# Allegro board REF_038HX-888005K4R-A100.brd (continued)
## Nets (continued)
D30105: D301.05
D30106: D301.06 SITE1.29(RXD1P)
D30107: D301.07
D30108: D301.08 SITE1.30(RXD1N)
D30109: D301.09
D30110: D301.10 SITE1.32(RXD2P)
D30111: D301.11
D30112: D301.12 SITE1.33(RXD2N)
D30113: D301.13
D30114: D301.14 SITE1.35(RXD3P)
D30115: D301.15
D30116: D301.16 SITE1.36(RXD3N)
D30201: D302.01
D30202: D302.02
D30203: D302.03
D30204: D302.04
D30205: D302.05
D30206: D302.06
D30207: D302.07
D30208: D302.08
D30209: D302.09
D30210: D302.10
D30211: D302.11
D30212: D302.12
D30213: D302.13
D30214: D302.14
D30215: D302.15
D30216: D302.16
D30501: D305.01
D30502: D305.02 SITE2.26(RXD0P)
D30503: D305.03
D30504: D305.04 SITE2.27(RXD0N)
D30505: D305.05
D30506: D305.06 SITE2.29(RXD1P)
D30507: D305.07
D30508: D305.08 SITE2.30(RXD1N)
D30509: D305.09
D30510: D305.10 SITE2.32(RXD2P)
D30511: D305.11
D30512: D305.12 SITE2.33(RXD2N)
D30513: D305.13
D30514: D305.14 SITE2.35(RXD3P)
D30515: D305.15
D30516: D305.16 SITE2.36(RXD3N)
D30601: D306.01
D30602: D306.02
D30603: D306.03
D30604: D306.04
D30605: D306.05
D30606: D306.06
D30607: D306.07
D30608: D306.08
D30609: D306.09
D30610: D306.10
D30611: D306.11
D30612: D306.12
D30613: D306.13
D30614: D306.14
D30615: D306.15
D30616: D306.16
DPS1_C1: DPS1.C01
DPS1_C5: DPS1.C05
DPS1_C11: DPS1.C11
DPS1_C15: DPS1.C15
DPS2_C1: DPS2.C01
DPS2_C5: DPS2.C05
DPS2_C11: DPS2.C11
DPS2_C15: DPS2.C15
DPS3_C1: DPS3.C01
DPS3_C5: DPS3.C05
DPS3_C11: DPS3.C11
DPS3_C15: DPS3.C15
DPS8_C1: DPS8.C01
DPS8_C5: DPS8.C05
DPS8_C11: DPS8.C11
DPS8_C15: DPS8.C15
MSDPS1_1F: DPS1.C03
MSDPS1_1GRD: DPS1.B02
MSDPS1_1GS: DPS1.A02
MSDPS1_1S: DPS1.C02
MSDPS1_2F: DPS1.C07
MSDPS1_2GRD: DPS1.B06
MSDPS1_2GS: DPS1.A06
MSDPS1_2S: DPS1.C06
MSDPS1_3F: DPS1.C13
MSDPS1_3GRD: DPS1.B12
MSDPS1_3GS: DPS1.A12
MSDPS1_3S: DPS1.C12
MSDPS1_4F: DPS1.C17
MSDPS1_4GRD: DPS1.B16
MSDPS1_4GS: DPS1.A16
MSDPS1_4S: DPS1.C16
MSDPS1_5F: DPS1.A03
MSDPS1_5GS: DPS1.B01
MSDPS1_5S: DPS1.B03
MSDPS1_6F: DPS1.A07
MSDPS1_6GS: DPS1.B05
MSDPS1_6S: DPS1.B07
MSDPS1_7F: DPS1.A13
MSDPS1_7GS: DPS1.B11
MSDPS1_7S: DPS1.B13
MSDPS1_8F: DPS1.A17
MSDPS1_8GS: DPS1.B15
MSDPS1_8S: DPS1.B17
MSDPS1_TR+: DPS1.A09
MSDPS1_TRVB-: DPS1.B09 SB1.2
MSDPS1_VB+: DPS1.C09
MSDPS2_1F: DPS2.C03
MSDPS2_1GRD: DPS2.B02
MSDPS2_1GS: DPS2.A02
MSDPS2_1S: DPS2.C02
MSDPS2_2F: DPS2.C07
MSDPS2_2GRD: DPS2.B06
MSDPS2_2GS: DPS2.A06
MSDPS2_2S: DPS2.C06
MSDPS2_3F: DPS2.C13
MSDPS2_3GRD: DPS2.B12
MSDPS2_3GS: DPS2.A12
MSDPS2_3S: DPS2.C12
MSDPS2_4F: DPS2.C17
MSDPS2_4GRD: DPS2.B16
MSDPS2_4GS: DPS2.A16
MSDPS2_4S: DPS2.C16
MSDPS2_5F: DPS2.A03
MSDPS2_5GS: DPS2.B01
MSDPS2_5S: DPS2.B03
MSDPS2_6F: DPS2.A07
MSDPS2_6GS: DPS2.B05
MSDPS2_6S: DPS2.B07
MSDPS2_7F: DPS2.A13
MSDPS2_7GS: DPS2.B11
MSDPS2_7S: DPS2.B13
MSDPS2_8F: DPS2.A17
MSDPS2_8GS: DPS2.B15
MSDPS2_8S: DPS2.B17
MSDPS2_TR+: DPS2.A09
MSDPS2_TRVB-: DPS2.B09 SB2.2
MSDPS2_VB+: DPS2.C09
MSDPS3_1F: DPS3.C03
MSDPS3_1GRD: DPS3.B02
MSDPS3_1GS: DPS3.A02
MSDPS3_1S: DPS3.C02
MSDPS3_2F: DPS3.C07
MSDPS3_2GRD: DPS3.B06
MSDPS3_2GS: DPS3.A06
MSDPS3_2S: DPS3.C06
MSDPS3_3F: DPS3.C13
MSDPS3_3GRD: DPS3.B12
MSDPS3_3GS: DPS3.A12
MSDPS3_3S: DPS3.C12
MSDPS3_4F: DPS3.C17
MSDPS3_4GRD: DPS3.B16
MSDPS3_4GS: DPS3.A16
MSDPS3_4S: DPS3.C16
MSDPS3_5F: DPS3.A03
MSDPS3_5GS: DPS3.B01
MSDPS3_5S: DPS3.B03
MSDPS3_6F: DPS3.A07
MSDPS3_6GS: DPS3.B05
MSDPS3_6S: DPS3.B07
MSDPS3_7F: DPS3.A13
MSDPS3_7GS: DPS3.B11
MSDPS3_7S: DPS3.B13
MSDPS3_8F: DPS3.A17
MSDPS3_8GS: DPS3.B15
MSDPS3_8S: DPS3.B17
MSDPS3_TR+: DPS3.A09
MSDPS3_TRVB-: DPS3.B09 SB3.2
MSDPS3_VB+: DPS3.C09
MSDPS8_1F: DPS8.C03
MSDPS8_1GRD: DPS8.B02
MSDPS8_1GS: DPS8.A02
MSDPS8_1S: DPS8.C02
MSDPS8_2F: DPS8.C07
MSDPS8_2GRD: DPS8.B06
MSDPS8_2GS: DPS8.A06
MSDPS8_2S: DPS8.C06
MSDPS8_3F: DPS8.C13
MSDPS8_3GRD: DPS8.B12
MSDPS8_3GS: DPS8.A12
MSDPS8_3S: DPS8.C12
MSDPS8_4F: DPS8.C17
MSDPS8_4GRD: DPS8.B16
MSDPS8_4GS: DPS8.A16
MSDPS8_4S: DPS8.C16
MSDPS8_5F: DPS8.A03
MSDPS8_5GS: DPS8.B01
MSDPS8_5S: DPS8.B03
MSDPS8_6F: DPS8.A07
MSDPS8_6GS: DPS8.B05
MSDPS8_6S: DPS8.B07
MSDPS8_7F: DPS8.A13
MSDPS8_7GS: DPS8.B11
MSDPS8_7S: DPS8.B13
MSDPS8_8F: DPS8.A17
MSDPS8_8GS: DPS8.B15
MSDPS8_8S: DPS8.B17
MSDPS8_TR+: DPS8.A09
MSDPS8_TRVB-: DPS8.B09 SB8.2
MSDPS8_VB+: DPS8.C09
S1_1AUX+: K9.4 R129.1
S1_1AUX-: K9.5 R130.1
S1_1SPI_CSN: K15.5 K19.6
S1_1SPI_SCK: K15.4 K19.3
S1_1SPI_SDI: K14.5 K20.6
S1_1SPI_SDO: K14.4 K20.3
S1_2AUX+: C3.1 R1.2 R3.1 R129.2
S1_2AUX-: C4.1 R2.2 R4.2 R130.2
S1_AUXCH+: K9.3 K12.3 SITE1.21(AUXCHP)
S1_AUXCH-: K9.6 K12.6 SITE1.20(AUXCHN)
S1_ISP_1LOCK: K33.3 R118.2
S1_SPI_1_CSN: K19.7 R87.1 U1.1(CS#)
S1_SPI_1_SCK: K19.2 R91.1 U1.6(SCLK)
S1_SPI_1_SDI: K20.7 R127.1
S1_SPI_1_SDO: K20.2 R125.1
S1_SPI_2_CSN: K19.5 R94.1 U2.1(CS#)
S1_SPI_2_SCK: K19.4 R98.1 U2.6(SCLK)
S1_SPI_2_SDI: K20.5 R128.1
S1_SPI_2_SDO: K20.4 R126.1
S1_SPI_11_SDI: R88.1 R127.2 U1.2(SO)
S1_SPI_11_SDO: R92.1 R125.2 U1.5(SI)
S1_SPI_22_SDI: R95.1 R128.2 U2.2(SO)
S1_SPI_22_SDO: R99.1 R126.2 U2.5(SI)
S1_SPI_CSN: K15.6 SITE1.43(SPI_CSN)
S1_SPI_SCK: K15.3 SITE1.42(SPI_SCK)
S1_SPI_SDI: K14.6 SITE1.44(SPI_SDI)
S1_SPI_SDO: K14.3 SITE1.41(SPI_SDO)
S1_XTAL_IN: K18.3 SITE1.109(XTAL_IN) TP_XTAL_IN.1(TP)
S1_XTAL_OUT: K18.6 SITE1.110(XTAL_OUT) TP_XTAL_OUT.1(TP)
S2_1AUX+: UNK2K9.4 UNK2R129.1
S2_1AUX-: UNK2K9.5 UNK2R130.1
S2_1SPI_CSN: UNK2K15.5 UNK2K19.6
S2_1SPI_SCK: UNK2K15.4 UNK2K19.3
S2_1SPI_SDI: UNK2K14.5 UNK2K20.6
S2_1SPI_SDO: UNK2K14.4 UNK2K20.3
S2_2AUX+: UNK2C3.1 UNK2R1.2 UNK2R3.1 UNK2R129.2
S2_2AUX-: UNK2C4.1 UNK2R2.2 UNK2R4.2 UNK2R130.2
S2_AUXCH+: SITE2.21(AUXCHP) UNK2K9.3 UNK2K12.3
S2_AUXCH-: SITE2.20(AUXCHN) UNK2K9.6 UNK2K12.6
S2_ISP_1LOCK: UNK2K33.3 UNK2R118.2
S2_SPI_1_CSN: UNK2K19.7 UNK2R87.1 UNK2U1.1
S2_SPI_1_SCK: UNK2K19.2 UNK2R91.1 UNK2U1.6
S2_SPI_1_SDI: UNK2K20.7 UNK2R127.1
S2_SPI_1_SDO: UNK2K20.2 UNK2R125.1
S2_SPI_2_CSN: UNK2K19.5 UNK2R94.1 UNK2U2.1
S2_SPI_2_SCK: UNK2K19.4 UNK2R98.1 UNK2U2.6
S2_SPI_2_SDI: UNK2K20.5 UNK2R128.1
S2_SPI_2_SDO: UNK2K20.4 UNK2R126.1
S2_SPI_11_SDI: UNK2R88.1 UNK2R127.2 UNK2U1.2
S2_SPI_11_SDO: UNK2R92.1 UNK2R125.2 UNK2U1.5
S2_SPI_22_SDI: UNK2R95.1 UNK2R128.2 UNK2U2.2
S2_SPI_22_SDO: UNK2R99.1 UNK2R126.2 UNK2U2.5
S2_SPI_CSN: SITE2.43(SPI_CSN) UNK2K15.6
S2_SPI_SCK: SITE2.42(SPI_SCK) UNK2K15.3
S2_SPI_SDI: SITE2.44(SPI_SDI) UNK2K14.6
S2_SPI_SDO: SITE2.41(SPI_SDO) UNK2K14.3
S2_XTAL_IN: SITE2.109(XTAL_IN) UNK2K18.3 UNK2TP_XTAL_IN.1
S2_XTAL_OUT: SITE2.110(XTAL_OUT) UNK2K18.6 UNK2TP_XTAL_OUT.1
SK1_2: SK1.2 SK1_2.1(TP)
SK1_3: SK1.3 SK1_3.1(TP)
SK1_4: SK1.4 SK1_4.1(TP)
SK1_5: SK1.5 SK1_5.1(TP)
SK1_6: SK1.6 SK1_6.1(TP)
SK1_7: SK1.7 SK1_7.1(TP)
SK2_2: SK2.2 SK2_2.1(TP)
SK2_3: SK2.3 SK2_3.1(TP)
SK2_4: SK2.4 SK2_4.1(TP)
SK2_5: SK2.5 SK2_5.1(TP)
SK2_6: SK2.6 SK2_6.1(TP)
SK2_7: SK2.7 SK2_7.1(TP)
UDBGND: BD29.2 BD30.2 BD31.2 BD32.2 BD33.2 BD34.2 BD35.2 BD36.2 BD37.2 BD38.2 BD39.2 BD40.2 CB1.2 CB2.2 CB3.2 CB4.2 CB5.2 CB6.2 CB7.2 CB8.2 CB19.1 LD902.2(B) UB1.1(A0) UB1.2(A1) UB1.3(A2) UB1.4(GND) UB1.7(WP) UTL1.A02 UTL1.A08 UTL1.A10 UTL1.A12 UTL1.A14 UTL1.B01 UTL1.B07 UTL1.B09 UTL1.B11 UTL1.B13 UTL2.A02 UTL2.A08 UTL2.A10 UTL2.A12 UTL2.A14 UTL2.B01 UTL2.B07 UTL2.B09 UTL2.B11 UTL2.B13 UTL3.A02 UTL3.A08 UTL3.A10 UTL3.A12 UTL3.A14 UTL3.B01 UTL3.B07 UTL3.B09 UTL3.B11 UTL3.B13 UTL4.A02 UTL4.A08 UTL4.A10 UTL4.A12 UTL4.A14 UTL4.B01 UTL4.B07 UTL4.B09 UTL4.B11 UTL4.B13
UT1_PDCF: UTL1.B15
UT1_PDCS: UTL1.A15
UT1_PGDS: UTL1.A16
UT1_PGRD: UTL1.B16
UT1_UP5V: BR902.1 CB1.1 CB2.1 CB3.1 CB4.1 CB5.1 CB6.1 CB7.1 CB8.1 CB19.2 CT1.2 K1.1(V+) K2.1(V+) K3.1(V+) K4.1(V+) K5.1(V+) K6.1(V+) K7.1(V+) K8.1(V+) K9.1(V+) K10.1(V+) K11.1(V+) K12.1(V+) K13.1(V+) K14.1(V+) K15.1(V+) K16.1(V+) K17.1(V+) K18.1(V+) K19.1(V+) K20.1(V+) K21.1(V+) K22.1(V+) K23.1(V+) K24.1(V+) K25.1(V+) K26.1(V+) K27.1(V+) K28.1(V+) K29.1(V+) K30.1(V+) K31.1(V+) K33.1(V+) K34.1(V+) K36.1(V+) K37.1(V+) K39.1(V+) K40.1(V+) K42.1(V+) RB1.1 RB2.1 RT1.1 RT2.1 RT5.2 RT6.2 RT7.1 RT8.1 SK1.1(V+) SK2.1(V+) UB1.8(VCC) UNK2CT1.2 UNK2K1.1 UNK2K2.1 UNK2K3.1 UNK2K4.1 UNK2K5.1 UNK2K6.1 UNK2K7.1 UNK2K8.1 UNK2K9.1 UNK2K10.1 UNK2K11.1 UNK2K12.1 UNK2K13.1 UNK2K14.1 UNK2K15.1 UNK2K16.1 UNK2K17.1 UNK2K18.1 UNK2K19.1 UNK2K20.1 UNK2K21.1 UNK2K22.1 UNK2K23.1 UNK2K24.1 UNK2K25.1 UNK2K26.1 UNK2K27.1 UNK2K28.1 UNK2K29.1 UNK2K30.1 UNK2K31.1 UNK2K33.1 UNK2K34.1 UNK2K36.1 UNK2K37.1 UNK2K39.1 UNK2K40.1 UNK2K42.1 UNK2RT1.1 UNK2RT2.1 UNK2RT5.2 UNK2RT6.2 UNK2RT7.1 UNK2RT8.1 UNK2SK1.1 UNK2SK2.1 UNK2UT1.8 UT1.8(VDD) UT_UP5V.1(TP) UTL1.A05 UTL1.B04 UTL2.A05 UTL2.B04 UTL3.A05 UTL3.B04 UTL4.A05 UTL4.B04
UT1_URW00: K13.8(V-) UTL1.A01
UT1_URW01: K28.8(V-) UTL1.B02
UT1_URW02: K14.8(V-) UTL1.A03
UT1_URW03: K33.8(V-) UTL1.B03
UT1_URW04: K20.8(V-) UTL1.A04
UT1_URW05: K10.8(V-) UTL1.B05
UT1_URW06: K15.8(V-) UTL1.A06
UT1_UW07: SK2.8(V-) UTL1.B06
UT1_UW08: K19.8(V-) UTL1.A07
UT1_UW09: K25.8(V-) K27.8(V-) UTL1.B08
UT1_UW10: K9.8(V-) UTL1.A09
UT1_UW11: K26.8(V-) UTL1.B10
UT1_UW12: K12.8(V-) UTL1.A11
UT1_UW13: SK1.8(V-) UTL1.B12
UT1_UW14: K23.8(V-) UTL1.A13
UT1_UW15: K22.8(V-) K24.8(V-) UTL1.B14
UT2_PDCF: UTL2.B15
UT2_PDCS: UTL2.A15
UT2_PGDS: UTL2.A16
UT2_PGRD: UTL2.B16
UT2_URW00: UNK2SK2.8 UTL2.A01
UT2_URW01: UNK2K25.8 UNK2K27.8 UTL2.B02
UT2_URW02: UNK2K10.8 UTL2.A03
UT2_URW03: UNK2K26.8 UTL2.B03
UT2_URW04: UNK2SK1.8 UTL2.A04
UT2_URW05: UNK2K22.8 UNK2K24.8 UTL2.B05
UT2_URW06: UNK2K33.8 UTL2.A06
UT2_UW07: UNK2K23.8 UTL2.B06
UT2_UW08: UNK2K28.8 UTL2.A07
UT2_UW09: UNK2K9.8 UTL2.B08
UT2_UW10: UNK2K13.8 UTL2.A09
UT2_UW11: UNK2K12.8 UTL2.B10
UT2_UW12: UNK2K14.8 UTL2.A11
UT2_UW13: UNK2K19.8 UTL2.B12
UT2_UW14: UNK2K20.8 UTL2.A13
UT2_UW15: UNK2K15.8 UTL2.B14
UT3_PDCF: UTL3.B15
UT3_PDCS: UTL3.A15
UT3_PGDS: UTL3.A16
UT3_PGRD: UTL3.B16
UT3_URW00: K30.8(V-) UTL3.A01
UT3_URW01: UNK2K3.8 UNK2K4.8 UTL3.B02
UT3_URW02: K21.8(V-) K29.8(V-) UTL3.A03
UT3_URW03: UNK2K1.8 UNK2K2.8 UTL3.B03
UT3_URW04: K16.8(V-) K17.8(V-) UTL3.A04
UT3_URW05: UNK2K5.8 UNK2K6.8 UTL3.B05
UT3_URW06: K7.8(V-) UTL3.A06
UT3_UW07: UNK2K7.8 UTL3.B06
UT3_UW08: K8.8(V-) K11.8(V-) UTL3.A07
UT3_UW09: UNK2K8.8 UNK2K11.8 UTL3.B08
UT3_UW10: K5.8(V-) K6.8(V-) UTL3.A09
UT3_UW11: UNK2K16.8 UNK2K17.8 UTL3.B10
UT3_UW12: K3.8(V-) K4.8(V-) UTL3.A11
UT3_UW13: UNK2K30.8 UTL3.B12
UT3_UW14: K1.8(V-) K2.8(V-) UTL3.A13
UT3_UW15: UNK2K21.8 UNK2K29.8 UTL3.B14
UT4_PDCF: UTL4.B15
UT4_PDCS: UTL4.A15
UT4_PGDS: UTL4.A16
UT4_PGRD: UTL4.B16
UT4_URW00: UNK2K37.12 UTL4.A01
UT4_URW01: UNK2K39.12 UTL4.B02
UT4_URW02: UNK2K42.12 UTL4.A03
UT4_URW03: UNK2K36.12 UTL4.B03
UT4_URW04: UNK2K34.12 UTL4.A04
UT4_URW05: UNK2K31.12 UTL4.B05
UT4_URW06: UNK2K40.12 UTL4.A06
UT4_UW07: UNK2K18.8 UTL4.B06
UT4_UW08: K37.12(V-) UTL4.A07
UT4_UW09: K18.8(V-) UTL4.B08
UT4_UW10: K39.12(V-) UTL4.A09
UT4_UW11: K34.12(V-) UTL4.B10
UT4_UW12: K42.12(V-) UTL4.A11
UT4_UW13: K40.12(V-) UTL4.B12
UT4_UW14: K36.12(V-) UTL4.A13
UT4_UW15: K31.12(V-) UTL4.B14
N23628089: BR902.2 LD902.1(A)
N24574244: J2.1 R89.1
N24574268: J3.1 R96.1
N24574272: J3.3 R93.1
N24574311: R90.1 U1.7(HOLD#)
N24574358: J2.2 U1.3(WP#)
N24574376: R97.1 U2.7(HOLD#)
N24574426: J3.2 U2.3(WP#)
N24574578: J2.3 R86.1
N24632959: J1.2 K10.4 R85.2 S1_RST_N.2 SW1.3 SW1.4
N24632988: C7.1 J1.1
N24641483: K25.3 R55.2
N24641485: K25.4 R56.1
N24641487: K25.6 R57.2
N24641489: K25.5 R58.1
N24641552: K26.3 R59.2
N24641554: K26.4 R60.1
N24641556: K26.6 R61.2
N24641558: K26.5 R62.1
N24641612: K27.5 R66.1
N24641614: K27.6 R65.2
N24642432: K22.6 R45.2
N24642434: K22.5 R46.1
N24642442: K23.3 R47.2
N24642444: K23.4 R48.1
N24642446: K23.6 R49.2
N24642448: K23.5 R50.1
N24642468: K24.3 R51.2
N24642486: K24.4 R52.1
N24642488: K24.6 R53.2
N24642490: K24.5 R54.1
N24780353: K12.4 R131.1
N24780370: K12.5 R132.1
N24787993: CA21.1 K34.5
N24789529: CA23.1 K36.5 K36.8
N24789779: CA24.1 K37.5
N24793751: RT3.1 RT5.1 UT1.3(A0)
N24793759: RT4.1 RT6.1 UT1.4(A1)
N24793795: RT7.2 UT1.6(CT)
N24793797: RT8.2 UT1.5(INT)
N25306310: K22.3 R102.2
N25306320: K22.4 R103.1
N25306354: K27.3 R104.2
N25306364: K27.4 R105.1
N25330426: CA29.1 K42.5
N25334489: CA26.1 K39.5
N25337760: CA34.1 K31.5
N25339188: CA27.1 K40.5
N25362248: K33.2 R82.1
N25362250: K33.4 R117.1
N25362465: K11.3 R39.2
N25362471: K11.4 R40.1
N25362509: K8.5 R38.1
N25362552: K8.3 R35.2
N25362554: K8.4 R36.1
N25362556: K8.6 R37.2
N25362573: K11.6 R41.2
N25362575: K11.5 R42.1
N25362658: K3.5 R18.1
N25362663: K3.6 R17.2
N25362668: K3.4 R16.1
N25362670: K3.3 R15.2
N25362705: K1.5 R10.1
N25362707: K1.6 R9.2
N25362709: K1.4 R8.1
N25362711: K1.3 R7.2
N25362734: K2.3 R11.2
N25362739: K2.4 R12.1
N25362741: K4.5 R22.1
N25362761: K4.3 R19.2
N25362763: K4.4 R20.1
N25362765: K4.6 R21.2
N25362815: K5.5 R26.1
N25362863: K5.3 R23.2
N25362865: K5.4 R24.1
N25362867: K5.6 R25.2
N25363066: K16.3 R67.2
N25363068: K16.4 R68.1
N25363070: K16.5 R70.1
N25363072: K16.6 R69.2
N25363098: K17.3 R71.2
N25363100: K17.4 R72.1
N25363118: K17.5 R74.1
N25363120: K17.6 R73.2
N25363130: K21.3 R75.2
N25363148: K21.4 R76.1
N25363150: K21.5 R78.1
N25363152: K21.6 R77.2
N25363178: K29.3 R79.2
N25363180: K29.4 R80.1
N25363198: K2.5 R14.1
N25363200: K2.6 R13.2
N25363358: K29.6 R43.2
N25363360: K29.5 R44.1
N25363376: K30.3 R63.2
N25363378: K30.4 R64.1
N25363404: K30.5 R101.1
N25363406: K30.6 R100.2
N25363469: K6.5 R30.1
N25363533: K6.3 R27.2
N25363535: K6.4 R28.1
N25363537: K6.6 R29.2
N25363539: K7.5 R34.1
N25363555: K7.3 R31.2
N25363557: K7.4 R32.1
N25363559: K7.6 R33.2
N25363681: K18.4 R5.1 R6.2
N25363685: K18.5 R6.1 R133.1
N25363701: C5.1 R133.2 Y1.1 Y2.1
N25363703: C6.1 R5.2 Y1.3 Y2.3
N25363863: K13.5 R120.2
N25363865: K13.4 R119.2
N25363959: J5.1 K28.5 R84.2
N25363975: J4.1 K28.4 R83.2
N25462044: CA37.1 K39.8
N25462912: CA40.1 K42.8
N25463486: CA28.1 K40.8
N25464528: CA25.1 K37.8
N25465136: CA22.1 K34.8
N25611014: UNK2J1.2 UNK2K10.4 UNK2R85.2 UNK2S1_RST_N.2
N25611025: UNK2C7.1 UNK2J1.1
N25611039: UNK2K25.3 UNK2R55.2
N25611040: UNK2K25.4 UNK2R56.1
N25611041: UNK2K25.6 UNK2R57.2
N25611042: UNK2K25.5 UNK2R58.1
N25611050: UNK2K26.3 UNK2R59.2
N25611051: UNK2K26.4 UNK2R60.1
N25611052: UNK2K26.6 UNK2R61.2
N25611053: UNK2K26.5 UNK2R62.1
N25611061: UNK2K27.5 UNK2R66.1
N25611062: UNK2K27.6 UNK2R65.2
N25611083: UNK2K22.6 UNK2R45.2
N25611084: UNK2K22.5 UNK2R46.1
N25611085: UNK2K23.3 UNK2R47.2
N25611086: UNK2K23.4 UNK2R48.1
N25611087: UNK2K23.6 UNK2R49.2
N25611088: UNK2K23.5 UNK2R50.1
N25611096: UNK2K24.3 UNK2R51.2
N25611097: UNK2K24.4 UNK2R52.1
N25611098: UNK2K24.6 UNK2R53.2
N25611099: UNK2K24.5 UNK2R54.1
N25611164: UNK2K12.4 UNK2R131.1
N25611166: UNK2K12.5 UNK2R132.1
N25611179: UNK2K22.3 UNK2R102.2
N25611180: UNK2K22.4 UNK2R103.1
N25611181: UNK2K27.3 UNK2R104.2
N25611182: UNK2K27.4 UNK2R105.1
N25611602: UNK2K33.2 UNK2R82.1
N25611603: UNK2K33.4 UNK2R117.1
N25611639: UNK2K11.3 UNK2R39.2
N25611640: UNK2K11.4 UNK2R40.1
N25611647: UNK2K8.5 UNK2R38.1
N25611655: UNK2K8.3 UNK2R35.2
N25611656: UNK2K8.4 UNK2R36.1
N25611657: UNK2K8.6 UNK2R37.2
N25611658: UNK2K11.6 UNK2R41.2
N25611659: UNK2K11.5 UNK2R42.1
N25611669: UNK2K3.5 UNK2R18.1
N25611670: UNK2K3.6 UNK2R17.2
N25611671: UNK2K3.4 UNK2R16.1
N25611672: UNK2K3.3 UNK2R15.2
N25611686: UNK2K1.5 UNK2R10.1
N25611687: UNK2K1.6 UNK2R9.2
N25611688: UNK2K1.4 UNK2R8.1
N25611689: UNK2K1.3 UNK2R7.2
N25611697: UNK2K2.3 UNK2R11.2
N25611700: UNK2K2.4 UNK2R12.1
N25611701: UNK2K4.5 UNK2R22.1
N25611709: UNK2K4.3 UNK2R19.2
N25611710: UNK2K4.4 UNK2R20.1
N25611711: UNK2K4.6 UNK2R21.2
N25611712: UNK2K5.5 UNK2R26.1
N25611720: UNK2K5.3 UNK2R23.2
N25611721: UNK2K5.4 UNK2R24.1
N25611722: UNK2K5.6 UNK2R25.2
N25611735: UNK2K16.3 UNK2R67.2
N25611736: UNK2K16.4 UNK2R68.1
N25611737: UNK2K16.5 UNK2R70.1
N25611738: UNK2K16.6 UNK2R69.2
N25611739: UNK2K17.3 UNK2R71.2
N25611740: UNK2K17.4 UNK2R72.1
N25611741: UNK2K17.5 UNK2R74.1
N25611742: UNK2K17.6 UNK2R73.2
N25611743: UNK2K21.3 UNK2R75.2
N25611744: UNK2K21.4 UNK2R76.1
N25611745: UNK2K21.5 UNK2R78.1
N25611746: UNK2K21.6 UNK2R77.2
N25611747: UNK2K29.3 UNK2R79.2
N25611748: UNK2K29.4 UNK2R80.1
N25611749: UNK2K2.5 UNK2R14.1
N25611750: UNK2K2.6 UNK2R13.2
N25611839: UNK2K29.6 UNK2R43.2
N25611840: UNK2K29.5 UNK2R44.1
N25611845: UNK2K30.3 UNK2R63.2
N25611846: UNK2K30.4 UNK2R64.1
N25611847: UNK2K30.5 UNK2R101.1
N25611848: UNK2K30.6 UNK2R100.2
N25611859: UNK2K6.5 UNK2R30.1
N25611867: UNK2K6.3 UNK2R27.2
N25611868: UNK2K6.4 UNK2R28.1
N25611869: UNK2K6.6 UNK2R29.2
N25611870: UNK2K7.5 UNK2R34.1
N25611878: UNK2K7.3 UNK2R31.2
N25611879: UNK2K7.4 UNK2R32.1
N25611880: UNK2K7.6 UNK2R33.2
N25611892: UNK2K18.4 UNK2R5.1 UNK2R6.2
N25611894: UNK2K18.5 UNK2R6.1 UNK2R133.1
N25611895: UNK2C5.1 UNK2R133.2 UNK2Y1.1 UNK2Y2.1
N25611896: UNK2C6.1 UNK2R5.2 UNK2Y1.3 UNK2Y2.3
N25611925: UNK2K13.5 UNK2R120.2
N25611926: UNK2K13.4 UNK2R119.2
N25611946: UNK2J5.1 UNK2K28.5 UNK2R84.2
N25611950: UNK2J4.1 UNK2K28.4 UNK2R83.2
N25615773: UNK2J2.1 UNK2R89.1
N25615777: UNK2J3.1 UNK2R96.1
N25615779: UNK2J3.3 UNK2R93.1
N25615786: UNK2R90.1 UNK2U1.7
N25615811: UNK2J2.2 UNK2U1.3
N25615820: UNK2R97.1 UNK2U2.7
N25615847: UNK2J3.2 UNK2U2.3
N25615858: UNK2J2.3 UNK2R86.1
N25616611: UNK2CA21.1 UNK2K34.5
N25616617: UNK2CA23.1 UNK2K36.5 UNK2K36.8
N25616622: UNK2CA24.1 UNK2K37.5
N25616748: UNK2CA29.1 UNK2K42.5
N25616755: UNK2CA26.1 UNK2K39.5
N25616834: UNK2CA34.1 UNK2K31.5
N25616842: UNK2CA27.1 UNK2K40.5
N25616987: UNK2CA37.1 UNK2K39.8
N25616993: UNK2CA40.1 UNK2K42.8
N25616997: UNK2CA28.1 UNK2K40.8
N25616999: UNK2CA25.1 UNK2K37.8
N25617005: UNK2CA22.1 UNK2K34.8
N25619537: UNK2RT3.1 UNK2RT5.1 UNK2UT1.3
N25619539: UNK2RT4.1 UNK2RT6.1 UNK2UT1.4
N25619557: UNK2RT7.2 UNK2UT1.6
N25619558: UNK2RT8.2 UNK2UT1.5

Pads without a net: CSDPS225 A17 B17 C17 D17; CSDPS229 A17 B17 C17 D17; CSDPS425 A17 B17 C17 D17; CSDPS429 A17 B17 C17 D17; D101/D501 A1 A2 A3 A4 A5 A6 A7 A8 A9 A10 A11 A12 A13 A14 A15 A16 A17 B1 B2 B3 B4 B5 B6 B7 B8 B9 B10 B11 B12 B13 B14 B15 B16 B17 C1 C2 C3 C4 C5 C6 C7 C8 C9 C10 C11 C12 C13 C14 C15 C16 C17 D2 D3 D4 D5 D6 D7 D8 D9 D10 D11 D12 D13 D14 D15 D16; D102 17 A17 B17; D103 17 A17 B17; D104 17 A17 B17; D105/D505 A1 A2 A3 A4 A5 A6 A7 A8 A9 A10 A11 A12 A13 A14 A15 A16 A17 B1 B2 B3 B4 B5 B6 B7 B8 B9 B10 B11 B12 B13 B14 B15 B16 B17 C1 C2 C3 C4 C5 C6 C7 C8 C9 C10 C11 C12 C13 C14 C15 C16 C17 D2 D3 D4 D5 D6 D7 D8 D9 D10 D11 D12 D13 D14 D15 D16; D106 17 A17 B17; D107 17 A17 B17; D108 17 A17 B17; D109 17 A17 B17; D110 17 A17 B17; D111 17 A17 B17; D112 17 A17 B17; D113 17 A17 B17; D114 17 A17 B17; D115 17 A17 B17; D116 17 A17 B17; D117 17 A17 B17; D118 17 A17 B17; D119 17 A17 B17; D120 17 A17 B17; D121 17 A17 B17; D122 17 A17 B17; D123 17 A17 B17; D124 17 A17 B17; D226 01 02 03 04 05 06 07 08 09 10 11 12 13 14 15 16 17; D227 01 02 03 04 05 06 07 08 09 10 11 12 13 14 15 16 17; D228 01 02 03 04 05 06 07 08 09 10 11 12 13 14 15 16 17; D230 01 02 03 05 06 07 08 09 10 11 12 13 14 15 16 17; D301 17 A17 B17; D302 17 A17 B17; D305 17 A17 B17; D306 17 A17 B17; D426 01 02 03 04 05 06 07 08 09 10 11 12 13 14 15 16 17; D427 01 02 03 04 05 06 07 08 09 10 11 12 13 14 15 16 17; D428 01 02 03 04 05 06 07 08 09 10 11 12 13 14 15 16 17; D430 01 02 03 04 05 06 07 08 09 10 11 12 13 14 15 16 17; DPS1 A04 A08 A10 A14 B04 B08 B10 B14 C04 C08 C10 C14; DPS2 A04 A08 A10 A14 B04 B08 B10 B14 C04 C08 C10 C14; DPS3 A04 A08 A10 A14 B04 B08 B10 B14 C04 C08 C10 C14; DPS8 A04 A08 A10 A14 B04 B08 B10 B14 C04 C08 C10 C14; FD1 1; FD2 1; FD3 1; FD4 1; FD5 1; FD6 1; FD7 1; FD8 1; HX8880-F05 1; JG_220919AA01 1; JG_220919AA02 1; K1 2 7; K2 2 7; K3 2 7; K4 2 7; K5 2 7; K6 2 7; K7 2 7; K8 2 7; K10 2 5 6 7; K11 2 7; K12 2 7; K13 2 7; K16 2 7; K17 2 7; K21 2 7; K22 2 7; K23 2 7; K24 2 7; K25 2 7; K26 2 7; K27 2 7; K28 2 7; K29 2 7; K30 2 7; K31 3 8 9 10; K33 5 6 7; K34 3 10; K36 3 10; K37 3 10; K39 3 10; K40 3 10; K42 3 10; LOGO1 1; LOGO2 1; LQFP176-20X20-P0.4 1; S1_I2C 3; SCREW1 GH1 GH2 GH3 GH4; SITE1 NUT1 NUT2 NUT3 NUT4; SITE2 NUT1 NUT2 NUT3 NUT4; SKB1 NUT1 NUT2 NUT3 NUT4; TPL1 1; TPL2 1; TPL3 1; TPL4 1; TPL5 1; TPL6 1; TPL7 1; TPL8 1; TPL9 1; TPL10 1; TPL11 1; TPL12 1; TPL13 1; TPL14 1; TPL15 1; TPL16 1; TPL17 1; TPL18 1; TPL19 1; TPL20 1; UNK2K1 2 7; UNK2K2 2 7; UNK2K3 2 7; UNK2K4 2 7; UNK2K5 2 7; UNK2K6 2 7; UNK2K7 2 7; UNK2K8 2 7; UNK2K10 2 5 6 7; UNK2K11 2 7; UNK2K12 2 7; UNK2K13 2 7; UNK2K16 2 7; UNK2K17 2 7; UNK2K21 2 7; UNK2K22 2 7; UNK2K23 2 7; UNK2K24 2 7; UNK2K25 2 7; UNK2K26 2 7; UNK2K27 2 7; UNK2K28 2 7; UNK2K29 2 7; UNK2K30 2 7; UNK2K31 3 8 9 10; UNK2K33 5 6 7; UNK2K34 3 10; UNK2K36 3 10; UNK2K37 3 10; UNK2K39 3 10; UNK2K40 3 10; UNK2K42 3 10; UNK2S1_I2C 3; UNK038HX-888005K4R-A100 1; UNK980HX-888005-KBH- 1; UTL1 A17 B17; UTL2 A17 B17; UTL3 A17 B17; UTL4 A17 B17

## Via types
v1: diameter 0.559, hole 0.305, TOP to BOTTOM, 2072 vias
v2: diameter 0.508, hole 0.305, TOP to BOTTOM, 286 vias
v3: diameter 0.559, hole 0.308, TOP to BOTTOM, 8 vias

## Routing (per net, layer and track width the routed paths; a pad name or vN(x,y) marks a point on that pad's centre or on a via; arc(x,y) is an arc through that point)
AGND: length 359.1
  TOP w0.203: SB1.1 v1(258.08,9.83) ; SB8.1 v1(34.56,419.44) ; SB3.1 v1(110.76,10.54) ; SB2.1 v1(184.42,418.97)
  TOP w0.231: SITE1.4 118.92,205.03 119.12,205.23 v1(119.12,205.36) ; v1(215.72,212.83) SITE2.62 ; SITE2.23 206.52,205.16 v1(206.45,205.23) ; SITE1.108 127.32,223.88 v1(127.03,223.59) ; SITE1.146 116.56,218.03 116.92,217.67 v1(116.92,217.43) ; SITE1.23 126.52,205.16 v1(126.45,205.23) ; SITE2.108 207.32,223.88 v1(207.03,223.59) ; 209.05,195.29 208.52,195.82 SITE2.28 ; 129.05,195.29 128.52,195.82 SITE1.28 ; SITE2.146 196.56,218.03 196.92,217.67 v1(196.92,217.43) ; v1(199.12,224.03) 199.32,224.23 SITE2.128 ; v1(119.12,224.03) 119.32,224.23 SITE1.128 ; v1(199.12,205.36) 199.12,205.23 198.92,205.03 SITE2.4 ; SITE2.34 210.92,200.48 215.35,196.05 215.35,195.81 ; v1(135.72,212.83) SITE1.62 ; v1(131.85,205.23) 132.12,205.23 132.52,204.83 SITE1.38 ; v1(211.85,205.23) 212.12,205.23 212.52,204.83 SITE2.38 ; SITE1.34 130.92,200.48 135.35,196.05 135.35,195.81
  TOP w0.381: UNK2CD17.2 v1(185.91,217.93) ; UNK2CD8.2 v1(206.55,194.73) ; CD21.2 v1(137.85,194.73) ; CD7.2 v1(147.73,212.64) ; UNK2CD15.2 v1(227.73,215.18) ; CD8.2 v1(126.55,194.73) ; UNK2CD25.2 v1(185.91,219.2) ; UNK2CD16.2 v1(209.21,235.56) ; CD13.2 v1(128.32,235.56) ; CD25.2 v1(105.91,219.2) ; CD5.2 v1(125.66,194.73) ; CD17.2 v1(105.91,217.93) ; CD4.2 v1(105.91,216.66) ; CD12.2 v1(123.06,235.56) ; UNK2CD6.2 v1(210.1,235.56) ; UNK2CD13.2 v1(208.32,235.56) ; UNK2CD11.2 v1(215.14,235.56) ; UNK2CD4.2 v1(185.91,216.66) ; UNK2CD5.2 v1(205.66,194.73) ; UNK2CD22.2 v1(204.77,194.73) ; UNK2CD1.2 v1(193.47,194.73) ; UNK2CD12.2 v1(203.06,235.56) ; UNK2CD21.2 v1(217.85,194.73) ; UNK2CD9.2 v1(212.26,194.73) ; CD1.2 v1(113.47,194.73) ; UNK2CD18.2 v1(227.73,213.91) ; CD23.2 v1(139.12,194.73) ; CD14.2 v1(126.54,235.56) ; UNK2CD19.2 v1(185.91,213.41) ; CD22.2 v1(124.77,194.73) ; CD9.2 v1(132.26,194.73) ; CD20.2 v1(147.73,211.37) ; CC28.2 v1(147.73,219.5) ; UNK2CD14.2 v1(206.54,235.56) ; UNK2CD7.2 v1(227.73,212.64) ; CD6.2 v1(130.1,235.56) ; CD19.2 v1(105.91,213.41) ; CD18.2 v1(147.73,213.91) ; UNK2CD20.2 v1(227.73,211.37) ; CD24.2 v1(105.91,223.69) ; UNK2CC28.2 v1(227.73,219.5) ; CD16.2 v1(129.21,235.56) ; UNK2CD3.2 v1(207.43,235.56) ; UNK2CD24.2 v1(185.91,223.69) ; CD15.2 v1(147.73,215.18) ; UNK2CD23.2 v1(219.12,194.73) ; CD11.2 v1(135.14,235.56) ; CD3.2 v1(127.43,235.56)
  TOP w0.508: UT1.7 v1(159.13,244.22) ; UNK2UT1.7 v1(239.13,244.22)
  L09_POWER w0.203: v1(152.49,215.34) 153.26,214.57 153.26,213.53 153.44,213.34 SH6.1 ; v1(235.53,221.63) 235.58,221.67 2SH11.1 ; SH26.1 105.65,220.34 105.91,220.08 v1(105.91,219.2) ; v1(232.49,215.34) 234.36,213.47 2SH6.1 ; 2SH26.1 185.63,220.34 185.91,220.05 185.91,219.2 v1(185.91,219.2) ; SH11.1 151.15,218.83 150.86,219.12 150.86,221.55 151.22,221.91 152.21,221.91 v1(152.49,221.63)
  L11_POWER w0.203: v1(135.14,235.56) 135.85,235.56 136.33,236.03 SH24.1 ; v1(207.03,223.59) 207.18,223.43 207.18,221.75 207.46,221.47 213.25,221.47 215.85,224.07 215.85,231.68 219.61,235.44 2SH17.1 ; v1(199.12,205.36) 196.84,205.36 195.61,204.12 2SH28.1 ; 2SH24.1 216.33,236.03 215.85,235.56 v1(215.14,235.56) ; SH17.1 139.61,235.44 135.85,231.68 135.85,224.07 133.25,221.47 127.46,221.47 127.18,221.75 127.18,223.43 v1(127.03,223.59) ; v1(111.98,206.12) 111.61,206.49 111.61,209.48 110.8,210.29 SH28.1
  L14_POWER w0.203: v1(143.6,243.82) 144.32,244.54 SH15.1 ; 2SH15.1 224.32,244.54 v1(223.6,243.82) ; SH13.1 140.82,245.47 139.74,244.39 v1(139.74,243.82) ; 2SH13.1 220.82,245.47 219.74,244.39 v1(219.74,243.82)
  L16_POWER w0.203: SH8.1 112.66,227.2 120.74,219.12 120.74,206.98 v1(119.12,205.36) ; SITE1.G6 130.95,213.46 130.95,221.05 131.53,221.63 SH9.1 ; v1(199.12,205.36) 198.56,204.8 198.56,198.57 196.87,196.88 2SH8.1 ; 2SH9.1 216.83,193.71 v1(217.85,194.73)
  L18_POWER w0.203: v1(188.99,205.89) 188.93,205.83 2SH2.1 ; SH2.1 97.05,204.25 98.09,203.2 109.68,203.2 111.59,205.12 111.59,205.73 v1(111.98,206.12) ; SH4.1 99.28,209.77 100.28,208.77 104.86,208.77 v1(105.68,209.59) ; 2SH4.1 185.2,209.11 v1(185.68,209.59)
  L20_SIGNAL w0.203: 2SH21.1 221.37,195.66 220.47,196.56 220.47,199.1 226.4,205.03 232.12,205.03 v1(232.68,204.47) ; SH21.1 136.63,197.07 136.92,197.36 138.07,197.36 138.46,196.96 138.46,195.39 v1(139.12,194.73) ; v1(207.28,133.35) 207.11,133.18 2SH19.1 ; v1(110.76,133.35) 111.82,134.41 SH19.1
  BOTTOM w0.381: CC33.2 v1(105.91,217.93) ; CC4.2 v1(124.77,194.73) ; CC35.2 v1(147.73,211.37) ; CC37.2 v1(105.91,223.69) CD24.2 ; UNK2CC13.2 v1(212.26,194.73) ; CC7.2 v1(147.73,212.64) ; UNK2CC1.2 v1(193.47,194.73) ; UNK2CC33.2 v1(185.91,217.93) ; UNK2CC8.2 v1(219.12,194.73) ; CC27.2 v1(135.14,235.56) CD11.2 ; UNK2CC26.2 v1(209.21,235.56) ; CC28.2 v1(147.73,219.5) CC16.2 ; CC19.2 v1(128.32,235.56) ; UNK2CC11.2 v1(206.55,194.73) ; UNK2CC32.2 v1(217.85,194.73) ; CC22.2 v1(126.54,235.56) ; UNK2CC35.2 v1(227.73,211.37) ; CD25.2 v1(105.91,219.2) CC39.2 ; CC11.2 v1(126.55,194.73) ; UNK2CD15.2 v1(227.73,215.18) UNK2CC40.2 ; UNK2CC28.2 v1(227.73,219.5) UNK2CC16.2 ; CC1.2 v1(113.47,194.73) ; UNK2CC17.2 v1(203.06,235.56) UNK2CD12.2 ; CC36.2 v1(130.1,235.56) ; CC30.2 v1(127.43,235.56) ; UNK2CC22.2 v1(206.54,235.56) ; CC32.2 v1(137.85,194.73) ; CD15.2 v1(147.73,215.18) CC40.2 ; UNK2CD19.2 v1(185.91,213.41) UNK2CC34.2 ; UNK2CC9.2 v1(185.91,216.66) ; UNK2CC36.2 v1(210.1,235.56) ; UNK2CC31.2 v1(227.73,213.91) ; CC26.2 v1(129.21,235.56) ; UNK2CC7.2 v1(227.73,212.64) ; UNK2CD25.2 v1(185.91,219.2) UNK2CC39.2 ; CC9.2 v1(105.91,216.66) ; CC8.2 v1(139.12,194.73) ; UNK2CD24.2 v1(185.91,223.69) UNK2CC37.2 ; CC6.2 v1(125.66,194.73) ; UNK2CC4.2 v1(204.77,194.73) ; UNK2CC30.2 v1(207.43,235.56) ; UNK2CD11.2 v1(215.14,235.56) UNK2CC27.2 ; CD12.2 v1(123.06,235.56) CC17.2 ; CC31.2 v1(147.73,213.91) ; CC34.2 v1(105.91,213.41) CD19.2 ; UNK2CC19.2 v1(208.32,235.56) ; UNK2CC6.2 v1(205.66,194.73) ; CC13.2 v1(132.26,194.73)
  BOTTOM w0.508: Y1.4 v1(92.41,247.23) ; Y1.2 v1(97.12,245.58) ; UNK2Y1.4 v1(172.41,247.23) ; UNK2Y1.2 v1(177.12,245.58)
  vias: v1(11.2,290.5) v1(14.24,285.75) v1(14.24,280.67) v1(14.24,275.59) v1(14.24,270.51) v1(14.24,265.43) v1(14.24,260.35) v1(14.24,255.27) v1(14.24,250.19) v1(14.24,245.11) v1(14.24,240.03) v1(14.24,189.23) v1(14.24,184.15) v1(14.24,179.07) v1(14.24,168.91) v1(14.24,163.83) v1(14.24,143.51) v1(14.59,153.59) v1(14.59,150.51) v1(14.59,147.42) v1(14.58,141.08) v1(17.34,284.81) v1(17.34,264.49) v1(17.34,244.17) v1(17.54,282.9) v1(17.54,280.36) v1(17.54,262.58) v1(17.54,260.04) v1(17.54,242.26) v1(17.54,239.72) v1(19.32,295.91) v1(19.32,290.83) v1(19.32,275.59) v1(19.32,270.51) v1(19.32,255.27) v1(19.32,250.19) v1(19.32,234.95) v1(19.32,189.23) v1(19.32,168.91) v1(19.32,163.83) v1(19.32,148.59) v1(19.32,143.51) v1(19.32,133.35) v1(24.4,295.91) v1(24.4,275.59) v1(24.4,255.27) v1(24.4,234.95) v1(24.4,214.63) v1(24.4,209.55) v1(24.4,204.47) v1(24.4,199.39) v1(24.4,194.31) v1(24.4,189.23) v1(24.4,184.15) v1(24.4,179.07) v1(24.4,173.99) v1(24.4,168.91) v1(24.4,163.83) v1(24.4,148.59) v1(24.4,143.51) v1(24.4,138.43) v1(24.4,133.35) v1(29.48,295.91) v1(29.48,290.83) v1(29.48,275.59) v1(29.48,270.51) v1(29.48,255.27) v1(29.48,250.19) v1(29.48,234.95) v1(29.48,229.87) v1(29.48,214.63) v1(29.48,209.55) v1(29.48,204.47) v1(29.48,199.39) v1(29.48,194.31) v1(29.48,189.23) v1(29.48,184.15) v1(29.48,179.07) v1(29.48,173.99) v1(29.48,148.59) v1(29.48,143.51) v1(29.48,138.43) v1(29.48,133.35) v1(30.67,282.9) v1(30.67,280.36) v1(30.67,262.58) v1(30.67,260.04) v1(30.67,242.26) v1(30.67,239.72) v1(30.67,221.94) v1(30.67,219.4) v1(30.87,284.81) v1(30.87,264.49) v1(30.87,244.17) v1(30.87,223.85) v1(33.57,295.51) v1(33.65,284.81) v1(33.65,244.17) v1(33.77,293.6) v1(33.85,282.9) v1(33.85,280.36) v1(33.85,242.26) v1(33.85,239.72) v1(34.56,290.83) v1(34.56,275.59) v1(34.56,270.51) v1(34.56,255.27) v1(34.56,250.19) v1(34.56,234.95) v1(34.56,229.87) v1(34.56,224.79) v1(34.56,219.71) v1(34.56,214.63) v1(34.56,209.55) v1(34.56,204.47) v1(34.56,199.39) v1(34.56,194.31) v1(34.56,189.23) v1(34.56,184.15) v1(34.56,179.07) v1(34.56,168.91) v1(34.56,163.83) v1(34.56,153.67) v1(34.56,148.59) v1(34.56,143.51) v1(34.56,138.43) v1(34.56,133.35) v1(39.64,275.59) v1(39.64,255.27) v1(39.64,234.95) v1(39.64,229.87) v1(39.64,224.79) v1(39.64,219.71) v1(39.64,214.63) v1(39.64,209.55) v1(39.64,204.47) v1(39.64,199.39) v1(39.64,168.91) v1(39.64,163.83) v1(39.64,158.75) v1(39.64,153.67) v1(39.64,148.59) v1(39.64,143.51) v1(39.64,138.43) v1(39.64,133.35) v1(44.72,290.83) v1(44.72,275.59) v1(44.72,270.51) v1(44.72,255.27) v1(44.72,250.19) v1(44.72,234.95) v1(44.72,229.87) v1(44.72,224.79) v1(44.72,219.71) v1(44.72,214.63) v1(44.72,209.55) v1(44.72,204.47) v1(44.72,199.39) v1(44.72,168.91) v1(44.72,163.83) v1(44.72,158.75) v1(44.72,153.67) v1(44.72,148.59) v1(44.72,143.51) v1(44.72,138.43) v1(44.72,133.35) v1(45.28,295.44) v1(45.41,185.97) v1(45.48,293.53) v1(46.98,282.9) v1(46.98,280.36) v1(46.98,262.58) v1(46.98,260.04) v1(46.98,242.26) v1(46.98,239.72) v1(47.18,284.81) v1(47.18,264.49) v1(47.18,244.17) v1(49.8,295.91) v1(49.8,290.83) v1(49.8,275.59) v1(49.8,270.51) v1(49.8,255.27) v1(49.8,250.19) v1(49.8,234.95) v1(49.8,229.87) v1(49.8,224.79) v1(49.8,219.71) v1(49.8,214.63) v1(49.8,209.55) v1(49.8,204.47) v1(49.8,199.39) v1(49.8,194.31) v1(49.8,189.23) v1(49.8,184.15) v1(49.8,179.07) v1(49.8,173.99) v1(49.8,168.91) v1(49.8,163.83) v1(49.8,158.75) v1(49.8,153.67) v1(49.8,148.59) v1(49.8,143.51) v1(49.8,138.43) v1(49.8,133.35) v1(49.95,264.49) v1(49.95,244.17) v1(50.15,262.58) v1(50.15,260.04) v1(50.15,242.26) v1(50.15,239.72) v1(50.36,284.81) v1(50.56,282.9) v1(50.56,280.36) v1(54.2,137.99) v1(54.88,295.91) v1(54.88,275.59) v1(54.88,255.27) v1(54.88,234.95) v1(54.88,214.63) v1(54.88,209.55) v1(54.88,204.47) v1(54.88,199.39) v1(54.88,194.31) v1(54.88,189.23) v1(54.88,184.15) v1(54.88,179.07) v1(54.88,173.99) v1(54.88,168.91) v1(54.88,163.83) v1(54.88,158.75) v1(54.88,153.67) v1(56.69,182.74) v1(59.96,295.91) v1(59.96,275.59) v1(59.96,255.27) v1(59.96,234.95) v1(59.96,214.63) v1(59.96,209.55) v1(59.96,204.47) v1(59.96,199.39) v1(59.96,194.31) v1(59.96,189.23) v1(59.96,184.15) v1(59.96,168.91) v1(59.96,163.83) v1(59.96,158.75) v1(59.96,153.67) v1(63.28,262.58) v1(63.28,260.04) v1(63.28,242.26) v1(63.28,239.72) v1(63.48,264.49) v1(63.48,244.17) v1(63.69,282.9) v1(63.69,280.36) v1(63.69,221.94) v1(63.69,219.4) v1(63.89,284.81) v1(63.89,223.85) v1(65.04,295.91) v1(65.04,290.83) v1(65.04,275.59) v1(65.04,270.51) v1(65.04,255.27) v1(65.04,250.19) v1(65.04,234.95) v1(65.04,229.87) v1(65.04,224.79) v1(65.04,219.71) v1(65.04,214.63) v1(65.04,209.55) v1(65.04,204.47) v1(65.04,199.39) v1(65.04,194.31) v1(65.04,189.23) v1(65.04,184.15) v1(65.04,168.91) v1(65.04,163.83) v1(65.04,158.75) v1(65.04,153.67) v1(66.06,142.42) v1(66.67,244.17) v1(66.87,242.26) v1(66.87,239.72) v1(70.12,295.91) v1(70.12,234.95) v1(70.12,229.87) v1(70.12,224.79) v1(70.12,219.71) v1(70.12,194.31) v1(70.12,189.23) v1(70.12,184.15) v1(70.12,179.07) v1(70.12,173.99) v1(70.12,168.91) v1(70.12,163.83) v1(70.12,158.75) v1(70.12,153.67) v1(70.86,137.99) v1(75.2,234.95) v1(75.2,229.87) v1(75.2,224.79) v1(75.2,219.71) v1(75.2,184.15) v1(75.2,179.07) v1(75.2,173.99) v1(75.2,168.91) v1(75.2,163.83) v1(75.2,158.75) v1(75.2,153.67) v1(76.25,205.14) v1(76.25,189.9) v1(76.75,295.51) v1(76.95,293.6) v1(79.75,217.54) v1(79.75,202.3) v1(80,262.58) v1(80,260.04) v1(80,242.26) v1(80,239.72) v1(80.2,264.49) v1(80.2,244.17) v1(80.28,234.95) v1(80.28,229.87) v1(80.28,224.79) v1(80.28,219.71) v1(80.28,184.15) v1(80.28,179.07) v1(80.28,173.99) v1(80.28,168.91) v1(80.28,163.83) v1(80.28,158.75) v1(80.28,153.67) v1(81.33,189.9) v1(81.33,186.69) v1(82.97,264.49) v1(83.17,262.58) v1(83.17,260.04) v1(84.16,198.7) v1(84.83,295.44) v1(85.03,293.53) v1(85.36,290.83) v1(85.36,250.19) v1(85.36,245.11) v1(85.36,240.03) v1(85.36,234.95) v1(85.36,229.87) v1(85.36,224.79) v1(85.36,219.71) v1(85.36,214.63) v1(85.36,210.69) v1(85.36,206.76) v1(85.36,202.82) v1(85.36,184.15) v1(85.36,179.07) v1(85.36,173.99) v1(85.36,168.91) v1(85.36,163.83) v1(85.36,158.75) v1(85.36,153.67) v1(85.77,142.42) v1(86.45,198.7) v1(86.45,193.62) v1(86.41,189.9) v1(86.41,186.69) v1(86.83,181.87) v1(86.83,167.65) v1(88.82,206.41) v1(89.91,202.3) v1(90.44,295.91) v1(90.44,290.83) v1(90.44,250.19) v1(90.44,245.11) v1(90.44,240.03) v1(90.44,234.95) v1(90.44,229.87) v1(90.44,224.79) v1(90.44,219.71) v1(90.44,214.63) v1(90.44,211.84) v1(90.44,209.58) v1(90.44,158.75) v1(90.44,153.67) v1(90.44,133.35) v1(91.49,189.9) v1(91.49,186.69) v1(93.42,207.73) v1(93.42,205.88) v1(94.99,202.3) v1(95.52,255.27) v1(95.52,250.19) v1(95.52,240.03) v1(95.52,234.95) v1(95.52,214.63) v1(95.52,211.84) v1(95.52,209.58) v1(95.52,133.35) v1(96.3,262.58) v1(96.3,260.04) v1(96.5,264.49) v1(96.49,229.67) v1(96.49,227.74) v1(96.49,225.81) v1(96.49,223.88) v1(96.49,221.57) v1(96.49,219.64) v1(97.22,249.49) v1(97.22,242.17) v1(98.83,207.74) v1(98.83,205.89) v1(98.83,204.03) v1(98.83,202.05) v1(98.95,188.98) v1(98.95,186.69) v1(98.91,183.1) v1(99.23,178.37) v1(99.23,164.15) v1(99.79,227.74) v1(99.79,225.81) v1(99.79,223.5) v1(99.79,221.57) v1(100.6,265.43) v1(100.6,260.35) v1(100.6,255.27) v1(100.6,211.84) v1(100.6,209.59) v1(100.6,133.35) v1(102.07,167.65) v1(102.36,172.32) v1(102.47,183.1) v1(102.43,179.51) v1(102.4,175.91) v1(102.5,188.98) v1(102.5,186.69) v1(103.91,207.74) v1(103.91,205.89) v1(103.91,204.03) v1(103.91,202.05) v1(105.68,265.43) v1(105.68,260.35) v1(105.68,255.27) v1(105.68,211.84) v1(105.68,158.75) v1(105.68,153.67) v1(105.68,133.35) v1(105.95,175.91) v1(106.06,188.98) v1(106.06,186.69) v1(106.02,183.1) v1(105.99,179.51) v1(106.21,172.1) v1(108.99,207.74) v1(108.99,205.89) v1(108.99,204.03) v1(108.99,202.05) v1(109.54,179.51) v1(109.62,188.98) v1(109.62,186.69) v1(109.58,183.1) v1(109.76,175.91) v1(109.8,295.11) v1(109.8,278.6) v1(110.76,265.43) v1(110.76,260.35) v1(110.76,255.27) v1(110.76,153.67) v1(111.38,241.09) v1(111.81,191.9) v1(113.14,183.1) v1(113.21,189.65) v1(113.17,186.69) v1(113.31,243.82) v1(113.31,241.09) v1(113.35,179.51) v1(113.48,204.65) v1(113.48,202.05) v1(113.48,199.95) v1(113.57,175.91) v1(114.47,164.15) v1(115.24,243.82) v1(115.24,241.09) v1(115.84,265.43) v1(115.84,260.35) v1(115.84,255.27) v1(115.84,250.19) v1(115.84,173.99) v1(115.84,168.91) v1(115.84,163.83) v1(115.84,158.75) v1(115.84,153.67) v1(115.84,143.51) v1(115.84,133.35) v1(116.76,190.28) v1(116.73,186.69) v1(116.95,183.1) v1(117.17,243.82) v1(117.17,241.09) v1(117.16,179.51) v1(119.06,163.88) v1(119.1,243.82) v1(119.1,241.09) v1(119.52,191.39) v1(120.06,150.42) v1(120.54,186.69) v1(120.76,183.1) v1(120.92,265.43) v1(120.92,260.35) v1(120.92,255.27) v1(120.92,250.19) v1(121.03,243.82) v1(121.03,241.09) v1(120.97,179.51) v1(121.68,191.39) v1(122.2,291.61) v1(122.2,275.1) v1(122.95,243.82) v1(122.95,241.09) v1(123.26,150.42) v1(123.84,191.39) v1(123.84,186.69) v1(124.26,163.88) v1(124.57,183.1) v1(124.59,205.23) v1(124.88,243.82) v1(124.88,241.09) v1(125.04,295.11) v1(125.04,278.6) v1(125.04,262.09) v1(126,250.19) v1(126,138.43) v1(126,133.35) v1(126.63,191.77) v1(126.63,189.23) v1(126.63,186.69) v1(126.63,184.15) v1(126.63,181.61) v1(126.63,179.07) v1(126.81,243.82) v1(126.81,241.09) v1(128.54,176.53) v1(128.74,241.09) v1(129.17,194.31) v1(129.17,191.77) v1(129.17,189.23) v1(129.17,186.69) v1(129.17,184.15) v1(129.17,181.61) v1(129.81,179.07) v1(130.09,243.82) v1(130.1,239.03) v1(130.1,237.66) v1(131.08,250.19) v1(131.08,173.99) v1(131.08,168.91) v1(131.08,138.43) v1(131.08,133.35) v1(132.02,243.82) v1(132.02,241.09) v1(132.26,191.77) v1(132.26,189.23) v1(132.26,186.69) v1(132.26,184.15) v1(132.26,181.61) v1(132.35,176.53) v1(133.62,179.07) v1(133.62,171.45) v1(133.95,243.82) v1(133.95,241.09) v1(134.89,173.99) v1(135.11,194.31) v1(135.11,191.77) v1(135.11,189.23) v1(135.11,186.69) v1(135.11,184.15) v1(135.11,181.61) v1(135.88,243.82) v1(135.88,241.09) v1(136.16,250.19) v1(136.16,176.53) v1(136.16,168.91) v1(136.16,138.43) v1(136.16,133.35) v1(137.44,291.61) v1(137.44,275.1) v1(137.44,258.59) v1(137.43,171.45) v1(137.56,179.07) v1(137.65,191.77) v1(137.65,189.23) v1(137.65,186.69) v1(137.65,184.15) v1(137.81,243.82) v1(137.81,241.09) v1(138.7,181.61) v1(138.7,173.99) v1(138.7,166.37) v1(139.74,241.09) v1(139.97,168.91) v1(140.1,176.53) v1(140.28,295.11) v1(140.28,278.6) v1(140.28,262.09) v1(141.24,250.19) v1(141.24,189.23) v1(141.24,184.15) v1(141.24,179.07) v1(141.24,171.45) v1(141.24,163.83) v1(141.24,158.75) v1(141.24,153.67) v1(141.24,148.59) v1(141.24,138.43) v1(141.24,133.35) v1(141.67,243.82) v1(141.67,241.09) v1(142.51,166.37) v1(142.64,173.99) v1(143.78,176.53) v1(143.78,168.91) v1(143.78,161.29) v1(145.05,163.83) v1(145.18,171.45) v1(146.32,250.19) v1(146.32,189.23) v1(146.32,184.15) v1(146.32,179.07) v1(146.32,173.99) v1(146.32,166.37) v1(146.32,158.75) v1(146.32,153.67) v1(146.32,148.59) v1(146.32,143.51) v1(146.32,138.43) v1(146.32,133.35) v1(147.57,241.81) v1(147.57,240.67) v1(147.59,161.29) v1(147.72,168.91) v1(148.86,171.45) v1(148.86,163.83) v1(148.86,156.21) v1(150.13,158.75) v1(150.26,166.37) v1(151.4,250.19) v1(151.4,189.23) v1(151.4,184.15) v1(151.4,179.07) v1(151.4,173.99) v1(151.4,168.91) v1(151.4,161.29) v1(151.4,153.67) v1(151.4,148.59) v1(151.4,143.51) v1(151.4,138.43) v1(151.4,133.35) v1(152.49,229.34) v1(152.49,227.41) v1(152.49,225.48) v1(152.49,223.56) v1(152.49,219.7) v1(152.49,217.27) v1(152.67,156.21) v1(152.68,291.61) v1(152.68,275.1) v1(152.68,258.59) v1(152.8,163.83) v1(153.94,166.37) v1(153.94,158.75) v1(153.94,151.13) v1(155.21,153.67) v1(155.34,161.29) v1(155.52,295.11) v1(155.52,278.6) v1(155.52,262.09) v1(155.53,227.41) v1(155.53,225.48) v1(155.53,223.56) v1(155.53,221.63) v1(155.53,219.19) v1(155.53,217.27) v1(156.25,205.14) v1(156.25,189.9) v1(156.48,250.19) v1(156.48,234.95) v1(156.48,229.87) v1(156.48,173.99) v1(156.48,168.91) v1(156.48,163.83) v1(156.48,156.21) v1(156.48,148.59) v1(156.48,143.51) v1(156.48,138.43) v1(156.48,133.35) v1(157.75,151.13) v1(157.88,158.75) v1(159.02,161.29) v1(159.02,153.67) v1(159.02,146.05) v1(159.75,217.54) v1(159.75,202.3) v1(160.29,148.59) v1(160.42,156.21) v1(161.56,250.19) v1(161.56,245.11) v1(161.56,240.03) v1(161.56,234.95) v1(161.56,229.87) v1(161.56,224.79) v1(161.56,219.71) v1(161.56,189.23) v1(161.56,173.99) v1(161.56,168.91) v1(161.56,163.83) v1(161.56,158.75) v1(161.56,151.13) v1(161.56,143.51) v1(161.56,138.43) v1(161.56,133.35) v1(162.83,146.05) v1(162.96,153.67) v1(164.16,198.7) v1(164.1,156.21) v1(164.1,148.59) v1(164.1,140.97) v1(164.16,88.9) v1(165.36,210.69) v1(165.36,206.76) v1(165.36,202.82) v1(165.37,143.51) v1(165.37,90.11) v1(165.37,87.69) v1(165.5,151.13) v1(166.45,193.62) v1(166.41,189.9) v1(166.54,224.32) v1(166.64,250.19) v1(166.64,245.11) v1(166.64,240.03) v1(166.64,234.95) v1(166.64,229.87) v1(166.64,214.63) v1(166.64,158.75) v1(166.64,153.67) v1(166.64,146.05) v1(166.64,138.43) v1(166.64,134.37) v1(166.64,131.83) v1(166.64,129.29) v1(166.64,126.75) v1(166.64,124.21) v1(166.64,121.67) v1(166.64,119.13) v1(166.64,116.59) v1(166.64,114.05) v1(166.64,111.51) v1(166.64,108.97) v1(166.64,106.43) v1(166.64,103.89) v1(166.58,88.9) v1(166.83,181.87) v1(166.83,167.65) v1(167.92,291.61) v1(167.92,275.1) v1(167.92,258.59) v1(167.91,140.97) v1(168.04,148.59) v1(168.82,206.41) v1(169.18,151.13) v1(169.18,143.51) v1(169.18,134.37) v1(169.18,131.83) v1(169.18,129.29) v1(169.18,126.75) v1(169.18,124.21) v1(169.18,121.67) v1(169.18,119.13) v1(169.18,116.59) v1(169.18,114.05) v1(169.18,111.51) v1(169.18,108.97) v1(169.18,106.43) v1(169.18,103.89) v1(169.24,88.9) v1(169.91,202.3) v1(170.44,211.84) v1(170.44,209.58) v1(170.45,138.43) v1(170.45,90.11) v1(170.45,87.69) v1(170.58,146.05) v1(170.76,295.11) v1(170.76,278.6) v1(170.76,262.09) v1(171.49,189.9) v1(171.66,88.9) v1(171.72,250.19) v1(171.72,245.11) v1(171.72,240.03) v1(171.72,234.95) v1(171.72,229.87) v1(171.72,224.79) v1(171.72,219.71) v1(171.72,214.63) v1(171.72,158.75) v1(171.72,153.67) v1(171.72,148.59) v1(171.72,140.97) v1(172.99,135.89) v1(173.12,143.51) v1(173.42,207.73) v1(173.42,205.88) v1(174.26,146.05) v1(174.26,138.43) v1(174.32,88.9) v1(174.99,202.3) v1(175.52,211.84) v1(175.52,209.58) v1(175.53,133.35) v1(175.53,90.11) v1(175.53,87.69) v1(175.66,140.97) v1(176.49,229.67) v1(176.49,227.74) v1(176.49,225.81) v1(176.49,223.88) v1(176.49,221.57) v1(176.49,219.64) v1(176.74,88.9) v1(176.8,240.03) v1(176.8,234.95) v1(176.8,153.67) v1(176.8,148.59) v1(176.8,143.51) v1(176.8,135.89) v1(176.81,129.29) v1(176.81,126.75) v1(176.81,124.21) v1(176.81,121.67) v1(176.81,119.13) v1(176.81,116.59) v1(176.81,114.05) v1(176.81,111.51) v1(176.81,108.97) v1(176.81,106.43) v1(176.81,103.89) v1(177.22,249.49) v1(177.22,242.17) v1(178.2,138.43) v1(178.83,207.74) v1(178.83,205.89) v1(178.83,204.03) v1(178.83,202.05) v1(178.95,188.98) v1(178.95,186.69) v1(178.91,183.1) v1(179.23,178.37) v1(179.23,164.15) v1(179.34,140.97) v1(179.34,133.35) v1(179.35,129.29) v1(179.35,126.75) v1(179.35,124.21) v1(179.35,121.67) v1(179.35,119.13) v1(179.35,116.59) v1(179.35,114.05) v1(179.35,111.51) v1(179.35,108.97) v1(179.35,106.43) v1(179.35,103.89) v1(179.4,88.9) v1(179.79,227.74) v1(179.79,225.81) v1(179.79,223.5) v1(179.79,221.57) v1(180.6,211.84) v1(180.6,209.59) v1(180.61,90.11) v1(180.61,87.69) v1(180.74,135.89) v1(181.82,88.9) v1(181.88,158.75) v1(181.88,153.67) v1(181.88,148.59) v1(181.88,143.51) v1(181.88,138.43) v1(181.88,130.81) v1(182.07,167.65) v1(182.36,172.32) v1(182.43,179.51) v1(182.4,175.91) v1(182.5,188.98) v1(182.5,186.69) v1(183.16,291.61) v1(183.16,275.1) v1(183.16,258.59) v1(183.28,133.35) v1(183.91,207.74) v1(183.91,205.89) v1(183.91,204.03) v1(183.91,202.05) v1(184.42,135.89) v1(184.42,128.27) v1(184.48,88.9) v1(185.68,211.84) v1(185.69,90.11) v1(185.69,87.69) v1(185.82,130.81) v1(185.95,175.91) v1(186.06,188.98) v1(186.06,186.69) v1(185.99,179.51) v1(186.21,172.1) v1(186.96,158.75) v1(186.96,153.67) v1(186.96,148.59) v1(186.96,143.51) v1(186.96,138.43) v1(186.96,133.35) v1(186.96,125.73) v1(186.94,124.21) v1(186.94,121.67) v1(186.94,119.13) v1(186.94,116.59) v1(186.94,114.05) v1(186.94,111.51) v1(186.94,108.97) v1(186.94,106.43) v1(186.94,103.89) v1(186.9,88.9) v1(188.36,128.27) v1(188.99,207.74) v1(188.99,204.03) v1(188.99,202.05) v1(189.54,179.51) v1(189.5,130.81) v1(189.48,124.21) v1(189.48,121.67) v1(189.48,119.13) v1(189.48,116.59) v1(189.48,114.05) v1(189.48,111.51) v1(189.48,108.97) v1(189.48,106.43) v1(189.48,103.89) v1(189.56,88.9) v1(189.62,188.98) v1(189.62,186.69) v1(189.58,183.1) v1(189.76,175.91) v1(189.8,295.11) v1(189.8,278.6) v1(189.8,262.09) v1(190.77,90.11) v1(190.77,87.69) v1(190.9,125.73) v1(191.38,241.09) v1(191.81,191.9) v1(191.98,206.12) v1(192.04,153.67) v1(192.04,148.59) v1(192.04,143.51) v1(192.04,138.43) v1(192.04,133.35) v1(192.04,128.27) v1(191.98,88.9) v1(193.14,183.1) v1(193.21,189.65) v1(193.17,186.69) v1(193.31,243.82) v1(193.31,241.09) v1(193.35,179.51) v1(193.44,123.19) v1(193.48,204.65) v1(193.48,202.05) v1(193.48,199.95) v1(193.57,175.91) v1(194.47,164.15) v1(194.58,125.73) v1(194.64,88.9) v1(195.24,243.82) v1(195.24,241.09) v1(195.84,173.99) v1(195.84,168.91) v1(195.85,90.11) v1(195.85,87.69) v1(195.98,120.65) v1(196.76,190.28) v1(196.73,186.69) v1(196.95,183.1) v1(197.06,88.9) v1(197.12,250.19) v1(197.17,243.82) v1(197.17,241.09) v1(197.16,179.51) v1(197.12,168.91) v1(197.12,163.83) v1(197.12,158.75) v1(197.12,153.67) v1(197.12,148.59) v1(197.12,143.51) v1(197.12,138.43) v1(197.12,133.35) v1(197.12,123.19) v1(197.12,119.13) v1(197.12,116.59) v1(197.12,114.05) v1(197.12,111.51) v1(197.12,108.97) v1(197.12,106.43) v1(197.12,103.89) v1(199.06,163.88) v1(199.1,243.82) v1(199.1,241.09) v1(199.52,191.39) v1(199.66,120.65) v1(199.66,119.13) v1(199.66,116.59) v1(199.66,114.05) v1(199.66,111.51) v1(199.66,108.97) v1(199.66,106.43) v1(199.66,103.89) v1(199.72,88.9) v1(200.06,150.42) v1(200.54,186.69) v1(200.76,183.1) v1(200.93,90.11) v1(200.93,87.69) v1(201.03,243.82) v1(201.03,241.09) v1(200.97,179.51) v1(201.68,191.39) v1(202.14,88.9) v1(202.2,291.61) v1(202.2,275.1) v1(202.2,258.59) v1(202.2,250.19) v1(202.95,243.82) v1(202.95,241.09) v1(203.26,150.42) v1(203.84,191.39) v1(203.84,186.69) v1(204.26,163.88) v1(204.57,183.1) v1(204.59,205.23) v1(204.88,243.82) v1(204.88,241.09) v1(205.04,295.11) v1(205.04,278.6) v1(205.3,262.09) v1(206.63,191.77) v1(206.63,189.23) v1(206.63,186.69) v1(206.63,184.15) v1(206.63,181.61) v1(206.63,179.07) v1(206.63,176.53) v1(206.63,173.99) v1(206.63,171.45) v1(206.63,168.91) v1(206.63,166.37) v1(206.63,163.83) v1(206.63,161.29) v1(206.63,158.75) v1(206.63,156.21) v1(206.63,153.67) v1(206.63,151.13) v1(206.63,148.59) v1(206.63,146.05) v1(206.63,143.51) v1(206.81,243.82) v1(206.81,241.09) v1(207.28,250.19) v1(207.9,140.97) v1(208.74,241.09) v1(209.17,194.31) v1(209.17,191.77) v1(209.17,189.23) v1(209.17,186.69) v1(209.17,184.15) v1(209.17,181.61) v1(209.17,179.07) v1(209.17,176.53) v1(209.17,173.99) v1(209.17,171.45) v1(209.17,168.91) v1(209.17,166.37) v1(209.17,163.83) v1(209.17,161.29) v1(209.17,158.75) v1(209.17,156.21) v1(209.17,153.67) v1(209.17,151.13) v1(209.17,148.59) v1(209.17,146.05) v1(209.17,143.51) v1(210.09,243.82) v1(210.1,239.03) v1(210.1,237.66) v1(210.44,138.43) v1(211.46,140.97) v1(211.71,186.69) v1(211.71,184.15) v1(211.71,181.61) v1(211.71,179.07) v1(211.71,176.53) v1(211.71,173.99) v1(211.71,171.45) v1(211.71,168.91) v1(211.71,166.37) v1(211.71,163.83) v1(211.71,161.29) v1(211.71,158.75) v1(211.71,156.21) v1(211.71,153.67) v1(211.71,151.13) v1(211.71,148.59) v1(211.71,146.05) v1(212.02,243.82) v1(212.02,241.09) v1(212.26,191.77) v1(212.26,189.23) v1(212.36,250.19) v1(212.36,133.35) v1(212.98,135.89) v1(213.95,243.82) v1(213.95,241.09) v1(214.25,138.43) v1(214.8,186.69) v1(215.11,194.31) v1(215.11,191.77) v1(215.52,133.35) v1(215.88,243.82) v1(215.88,241.09) v1(216.79,135.89) v1(217.34,184.15) v1(217.44,295.91) v1(217.44,291.61) v1(217.44,275.1) v1(217.44,250.19) v1(217.65,191.77) v1(217.7,258.59) v1(217.81,243.82) v1(217.81,241.09) v1(218.06,130.81) v1(218.19,138.43) v1(218.31,187.71) v1(219.2,190.25) v1(219.33,133.35) v1(219.74,241.09) v1(219.88,181.61) v1(220.54,262.09) v1(220.73,135.89) v1(220.85,185.17) v1(221.67,243.82) v1(221.67,241.09) v1(221.74,187.71) v1(221.87,130.81) v1(222.42,179.07) v1(222.52,295.91) v1(222.52,290.83) v1(222.52,275.59) v1(222.52,250.19) v1(223.27,133.35) v1(223.39,182.63) v1(224.28,185.17) v1(224.96,176.53) v1(225.81,130.81) v1(225.93,180.09) v1(226.82,182.63) v1(227.5,173.99) v1(227.6,295.91) v1(227.6,290.83) v1(227.6,275.59) v1(227.6,250.19) v1(227.57,241.81) v1(227.57,240.67) v1(227.6,168.91) v1(227.6,163.83) v1(227.6,133.35) v1(228.47,177.55) v1(229.15,206.57) v1(229.36,180.09) v1(230.04,171.45) v1(230.76,118.11) v1(230.89,125.73) v1(231.01,175.01) v1(231.9,177.55) v1(232.03,120.65) v1(232.49,229.34) v1(232.49,227.41) v1(232.49,225.48) v1(232.49,223.56) v1(232.49,221.63) v1(232.49,219.7) v1(232.49,217.27) v1(232.58,168.91) v1(232.68,295.91) v1(232.68,290.83) v1(232.68,250.19) v1(232.68,234.95) v1(232.68,209.55) v1(232.68,199.39) v1(232.68,194.31) v1(232.68,189.23) v1(232.68,184.15) v1(232.68,163.83) v1(232.68,133.35) v1(232.94,258.59) v1(233.3,115.57) v1(233.43,123.19) v1(233.55,172.47) v1(234.44,175.01) v1(234.57,118.11) v1(235.12,166.37) v1(235.53,227.41) v1(235.53,225.48) v1(235.53,223.56) v1(235.53,219.19) v1(235.53,217.27) v1(235.78,262.09) v1(235.84,113.03) v1(235.97,120.65) v1(236.09,169.93) v1(236.98,172.47) v1(237.11,115.57) v1(237.66,163.83) v1(237.76,250.19) v1(237.76,234.95) v1(237.76,229.87) v1(237.76,224.79) v1(237.76,219.71) v1(237.76,214.63) v1(237.76,209.55) v1(237.76,199.39) v1(237.76,189.23) v1(237.76,133.35) v1(237.82,88.9) v1(238.38,110.49) v1(238.51,118.11) v1(238.63,167.39) v1(239.03,90.11) v1(239.03,87.69) v1(239.52,169.93) v1(239.65,113.03) v1(240.2,161.29) v1(240.24,88.9) v1(240.3,106.43) v1(240.3,103.89) v1(241.05,115.57) v1(241.17,164.85) v1(242.06,167.39) v1(242.19,110.49) v1(242.74,158.75) v1(242.84,250.19) v1(242.84,245.11) v1(242.84,240.03) v1(242.84,234.95) v1(242.84,229.87) v1(242.84,224.79) v1(242.84,219.71) v1(242.84,133.35) v1(242.84,106.43) v1(242.84,103.89) v1(242.9,88.9) v1(243.59,113.03) v1(243.71,162.31) v1(244.11,90.11) v1(244.11,87.69) v1(244.6,164.85) v1(244.73,107.95) v1(245.28,156.21) v1(245.32,88.9) v1(246.13,110.49) v1(246.25,159.77) v1(247.17,176.56) v1(247.14,162.31) v1(247.22,207.05) v1(247.27,105.41) v1(247.82,153.67) v1(247.92,250.19) v1(247.92,245.11) v1(247.92,240.03) v1(247.92,234.95) v1(247.92,229.87) v1(247.92,224.79) v1(247.92,219.71) v1(247.92,148.59) v1(247.92,143.51) v1(247.92,138.43) v1(247.92,133.35) v1(247.98,88.9) v1(248.18,258.59) v1(248.67,107.95) v1(248.79,157.23) v1(249.19,90.11) v1(249.19,87.69) v1(249.68,159.77) v1(250.36,151.13) v1(250.4,88.9) v1(251.02,295.11) v1(251.02,278.6) v1(251.02,262.09) v1(251.21,105.41) v1(251.33,154.69) v1(252.22,157.23) v1(253,250.19) v1(253,245.11) v1(253,240.03) v1(253,234.95) v1(253,229.87) v1(253,224.79) v1(253,219.71) v1(253,214.63) v1(253,209.55) v1(253,204.47) v1(253,199.39) v1(253,194.31) v1(252.98,149.61) v1(253,143.51) v1(253,138.43) v1(253,133.35) v1(253.06,88.9) v1(253.87,152.15) v1(254.27,90.11) v1(254.27,87.69) v1(254.76,154.69) v1(255.52,147.07) v1(255.48,88.9) v1(256.41,149.61) v1(256.47,203.82) v1(257.3,152.15) v1(258.06,144.53) v1(258.08,250.19) v1(258.08,245.11) v1(258.08,240.03) v1(258.08,234.95) v1(258.08,229.87) v1(258.08,204.47) v1(258.08,138.43) v1(258.08,133.35) v1(258.14,88.9) v1(258.95,147.07) v1(259.35,90.11) v1(259.35,87.69) v1(259.84,149.61) v1(260.56,88.9) v1(260.6,141.99) v1(260.6,139.45) v1(260.6,136.91) v1(260.6,134.37) v1(260.6,131.83) v1(260.6,129.29) v1(260.6,126.75) v1(260.6,124.21) v1(260.6,121.67) v1(260.6,119.13) v1(260.6,116.59) v1(260.6,114.05) v1(260.6,111.51) v1(260.6,108.97) v1(260.6,106.43) v1(260.6,103.89) v1(261.49,144.53) v1(262.07,180.99) v1(262.38,147.07) v1(263.16,250.19) v1(263.16,245.11) v1(263.16,240.03) v1(263.16,234.95) v1(263.16,229.87) v1(263.16,209.55) v1(263.16,153.67) v1(263.14,141.99) v1(263.14,139.45) v1(263.14,136.91) v1(263.14,134.37) v1(263.14,131.83) v1(263.14,129.29) v1(263.14,126.75) v1(263.14,124.21) v1(263.14,121.67) v1(263.14,119.13) v1(263.14,116.59) v1(263.14,114.05) v1(263.14,111.51) v1(263.14,108.97) v1(263.14,106.43) v1(263.14,103.89) v1(263.22,88.9) v1(263.42,291.61) v1(263.42,275.1) v1(263.42,258.59) v1(264.43,90.11) v1(264.43,87.69) v1(264.92,144.53) v1(265.64,88.9) v1(266.26,295.11) v1(266.26,278.6) v1(266.26,262.09) v1(266.57,139.45) v1(266.88,176.56) v1(267.46,141.99) v1(268.24,250.19) v1(268.24,245.11) v1(268.24,240.03) v1(268.24,234.95) v1(268.24,229.87) v1(268.24,209.55) v1(268.24,204.47) v1(268.24,199.39) v1(268.24,194.31) v1(268.24,153.67) v1(268.24,148.59) v1(268.3,88.9) v1(269.11,136.91) v1(269.51,90.11) v1(269.51,87.69) v1(270,139.45) v1(270.72,88.9) v1(270.78,134.37) v1(270.78,131.83) v1(270.78,129.29) v1(270.78,126.75) v1(270.78,124.21) v1(270.78,121.67) v1(270.78,119.13) v1(270.78,116.59) v1(270.78,114.05) v1(270.78,111.51) v1(270.78,108.97) v1(270.78,106.43) v1(270.78,103.89) v1(272.54,136.91) v1(273.32,250.19) v1(273.32,245.11) v1(273.32,194.31) v1(273.32,153.67) v1(273.32,148.59) v1(273.32,143.51) v1(273.32,134.37) v1(273.32,131.83) v1(273.32,129.29) v1(273.32,126.75) v1(273.32,124.21) v1(273.32,121.67) v1(273.32,119.13) v1(273.32,116.59) v1(273.32,114.05) v1(273.32,111.51) v1(273.32,108.97) v1(273.32,106.43) v1(273.32,103.89) v1(273.38,88.9) v1(274,140.21) v1(274.59,90.11) v1(274.59,87.69) v1(275.8,88.9) v1(276.33,152.67) v1(276.33,149.59) v1(276.33,146.5) v1(278.66,291.61) v1(278.66,275.1) v1(278.66,258.59) v1(278.74,180.99) v2(275.26,241.58) v2(278.21,249.53) v2(278.21,246.45) v3(220.6,128.27) v3(223.14,125.73) v3(224.41,128.27) v3(225.68,123.19) v3(226.95,125.73) v3(228.22,120.65) v3(228.35,128.27) v3(229.49,123.19)
